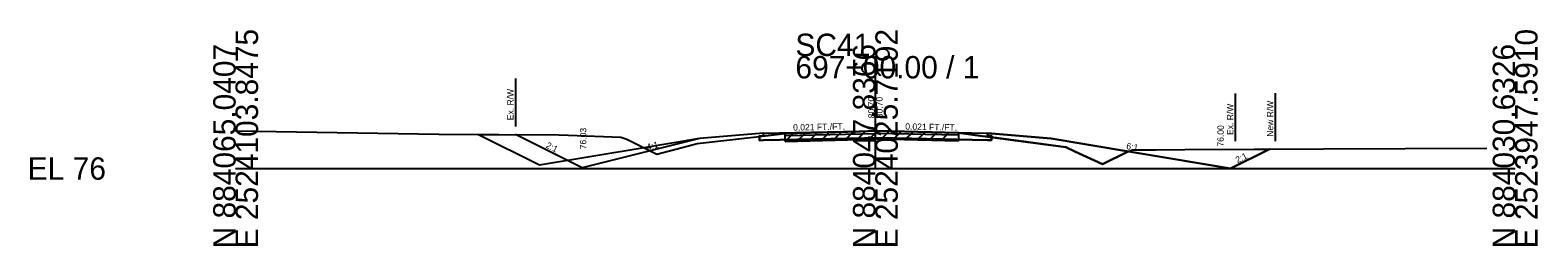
# Model space of a CAD drawing. Extents: x -26 to 183, y -10 to 24021.
# Drawn here: x -25.7 to 162.8, y 20490.3 to 20517.3 of the extents above; entities that cross this region are included whole.
import ezdxf

# ---------------------------------------------------------------- set-up
doc = ezdxf.new("R2010")
doc.units = 0
for name, color, linetype in [('RD_GPK_XS_Cell', 7, 'Continuous'), ('RD_XS_Base', 7, 'Continuous'), ('RD_XS_Buildup', 7, 'Continuous'), ('RD_XS_EarthShd', 7, 'Continuous'), ('RD_XS_EwShp', 7, 'Continuous'), ('RD_XS_ExGround', 7, 'Continuous'), ('RD_XS_ExPaveRet', 7, 'Continuous'), ('RD_XS_ExRW', 7, 'Continuous'), ('RD_XS_NewRW', 7, 'Continuous'), ('RD_XS_Pave', 7, 'Continuous'), ('RD_XS_TieSlope', 7, 'Continuous'), ('RD_XS_TX_Elev_EX', 7, 'Continuous'), ('RD_XS_TX_Elev_PR', 7, 'Continuous'), ('RD_XS_TX_Slope', 7, 'Continuous')]:
    doc.layers.add(name, color=color, linetype=linetype)

msp = doc.modelspace()

# ---------------------------------------------------------------- linework, layer by layer
at = {"layer": 'RD_GPK_XS_Cell'}
for p, q in [((80, 20500), (80, 20514.09)), ((0, 20500), (80, 20500)), ((80, 20500), (160, 20500))]:
    msp.add_line(p, q, dxfattribs=at)
at = {"layer": 'RD_XS_Base'}
for p in [(66.01, 20503.54), (93.99, 20503.57)]:
    msp.add_line(p, (80.72, 20503.84), dxfattribs=at)
at = {"layer": 'RD_XS_Buildup'}
for p in [(68.74, 20504.15), (90.4, 20504.16)]:
    msp.add_line(p, (80, 20504.38), dxfattribs=at)
at = {"layer": 'RD_XS_EarthShd'}
for p, q in [((66, 20504.41), (58, 20503.74)), ((94, 20504.41), (102, 20503.74))]:
    msp.add_line(p, q, dxfattribs=at)
at = {"layer": 'RD_XS_EwShp'}
for points in [[(30.29, 20504.27), (40.43, 20504.2), (41.62, 20504.18), (48.19, 20503.94), (48.94, 20503.66), (51.08, 20502.59), (38, 20500.41)], [(41.62, 20504.18), (48.19, 20503.94), (48.94, 20503.66), (51.08, 20502.59), (38, 20500.41), (30.29, 20504.27), (40.43, 20504.2)], [(41.62, 20504.18), (48.19, 20503.94), (48.94, 20503.66), (51.08, 20502.59), (38, 20500.41), (30.29, 20504.27), (40.43, 20504.2)], [(58, 20503.74), (51.08, 20502.59), (52.69, 20501.78), (56.63, 20502.83), (57.73, 20503.14), (65.5, 20504.03), (65.5, 20504.08), (66, 20504.09), (66, 20504.41)], [(66, 20504.09), (66, 20504.41), (58, 20503.74), (51.08, 20502.59), (52.69, 20501.78), (56.63, 20502.83), (57.73, 20503.14), (65.5, 20504.03), (65.5, 20504.08)], [(66, 20504.09), (66, 20504.41), (58, 20503.74), (51.08, 20502.59), (52.69, 20501.78), (56.63, 20502.83), (57.73, 20503.14), (65.5, 20504.03), (65.5, 20504.08)], [(65.5, 20503.53), (65.5, 20504.03), (66, 20504.09), (66.6, 20504.15), (68.74, 20504.4), (78.1, 20504.65), (80.08, 20504.7), (81.92, 20504.66), (90.4, 20504.48), (93.41, 20504.06), (94.5, 20503.92), (94.5, 20503.56), (93.99, 20503.57), (80.72, 20503.84), (66.01, 20503.54)], [(94.5, 20503.56), (94.5, 20503.92), (93.41, 20504.06), (90.4, 20504.48), (81.92, 20504.66), (80.08, 20504.7), (78.1, 20504.65), (68.74, 20504.4), (66.6, 20504.15), (66, 20504.09), (65.5, 20504.03), (65.5, 20503.53), (66.01, 20503.54), (80.72, 20503.84), (93.99, 20503.57)], [(94.5, 20503.56), (94.5, 20503.92), (93.41, 20504.06), (90.4, 20504.48), (81.92, 20504.66), (80.08, 20504.7), (78.1, 20504.65), (68.74, 20504.4), (66.6, 20504.15), (66, 20504.09), (65.5, 20504.03), (65.5, 20503.53), (66.01, 20503.54), (80.72, 20503.84), (93.99, 20503.57)], [(94.5, 20504.11), (94, 20504.12), (94, 20504.41), (102, 20503.74), (111.66, 20502.13), (111.52, 20502.07), (108.41, 20500.53), (104.95, 20502.12), (103.83, 20502.68), (94.5, 20503.92)], [(104.95, 20502.12), (108.41, 20500.53), (111.52, 20502.07), (111.66, 20502.13), (102, 20503.74), (94, 20504.41), (94, 20504.12), (94.5, 20504.11), (94.5, 20503.92), (103.83, 20502.68)], [(104.95, 20502.12), (108.41, 20500.53), (111.52, 20502.07), (111.66, 20502.13), (102, 20503.74), (94, 20504.41), (94, 20504.12), (94.5, 20504.11), (94.5, 20503.92), (103.83, 20502.68)], [(111.66, 20502.13), (112.15, 20502.35), (115.1, 20502.35), (118.68, 20502.38), (129.27, 20502.43), (124.42, 20500.01)], [(111.66, 20502.13), (112.15, 20502.35), (115.1, 20502.35), (118.68, 20502.38), (129.27, 20502.43), (124.42, 20500.01)], [(111.66, 20502.13), (112.15, 20502.35), (115.1, 20502.35), (118.68, 20502.38), (129.27, 20502.43), (124.42, 20500.01)]]:
    msp.add_lwpolyline(points, close=True, dxfattribs=at)
at = {"layer": 'RD_XS_ExGround'}
for p, q in [((0, 20504.7), (25.4, 20504.3)), ((25.4, 20504.3), (40.43, 20504.2)), ((40.43, 20504.2), (41.62, 20504.18)), ((41.62, 20504.18), (48.19, 20503.94)), ((48.19, 20503.94), (48.94, 20503.66)), ((48.94, 20503.66), (52.69, 20501.78)), ((56.63, 20502.83), (57.73, 20503.14)), ((57.73, 20503.14), (66.6, 20504.15)), ((66.6, 20504.15), (68.74, 20504.4)), ((68.74, 20504.4), (78.1, 20504.65)), ((78.1, 20504.65), (80.08, 20504.7)), ((80.08, 20504.7), (81.92, 20504.66)), ((81.92, 20504.66), (90.4, 20504.48)), ((90.4, 20504.48), (93.41, 20504.06)), ((93.41, 20504.06), (103.83, 20502.68)), ((52.69, 20501.78), (56.63, 20502.83)), ((103.83, 20502.68), (104.95, 20502.12)), ((104.95, 20502.12), (108.41, 20500.53)), ((108.41, 20500.53), (111.52, 20502.07)), ((111.52, 20502.07), (112.15, 20502.35)), ((112.15, 20502.35), (115.1, 20502.35)), ((115.1, 20502.35), (118.68, 20502.38)), ((118.68, 20502.38), (136.04, 20502.46)), ((136.04, 20502.46), (156.45, 20502.53))]:
    msp.add_line(p, q, dxfattribs=at)
at = {"layer": 'RD_XS_ExPaveRet'}
for p, q in [((68.74, 20503.4), (69.76, 20504.43)), ((68.74, 20503.4), (68.74, 20504.4)), ((68.74, 20503.4), (78.1, 20503.65)), ((70.24, 20503.44), (71.26, 20504.47)), ((71.74, 20503.48), (72.76, 20504.51)), ((73.24, 20503.52), (74.26, 20504.55)), ((74.74, 20503.56), (75.76, 20504.58)), ((76.24, 20503.6), (77.26, 20504.62)), ((77.74, 20503.64), (78.76, 20504.66)), ((78.1, 20503.65), (80.08, 20503.7)), ((79.24, 20503.68), (80.26, 20504.69)), ((80.08, 20503.7), (81.92, 20503.66)), ((80.74, 20503.68), (81.72, 20504.66)), ((81.92, 20503.66), (90.4, 20503.48)), ((82.24, 20503.65), (83.22, 20504.63)), ((83.74, 20503.62), (84.72, 20504.6)), ((85.24, 20503.59), (86.22, 20504.57)), ((86.74, 20503.56), (87.72, 20504.54)), ((88.24, 20503.53), (89.22, 20504.51)), ((90.4, 20504.48), (90.4, 20503.48))]:
    msp.add_line(p, q, dxfattribs=at)
at = {"layer": 'RD_XS_ExRW'}
for p, q in [((35, 20511.27), (35, 20505.27)), ((125, 20509.41), (125, 20503.41))]:
    msp.add_line(p, q, dxfattribs=at)
at = {"layer": 'RD_XS_NewRW'}
msp.add_line((130.01, 20509.44), (130.01, 20503.44), dxfattribs=at)
at = {"layer": 'RD_XS_Pave'}
for p, q in [((65.5, 20504.08), (66, 20504.09)), ((65.5, 20503.53), (65.5, 20504.08)), ((65.5, 20503.53), (66.01, 20503.54)), ((66, 20504.41), (80, 20504.7)), ((66, 20504.09), (66, 20504.41)), ((80, 20504.7), (94, 20504.41)), ((94.5, 20503.56), (93.99, 20503.57)), ((94, 20504.12), (94, 20504.41)), ((94.5, 20504.11), (94, 20504.12)), ((94.5, 20503.56), (94.5, 20504.11))]:
    msp.add_line(p, q, dxfattribs=at)
at = {"layer": 'RD_XS_TieSlope'}
for p, q in [((43.33, 20500.07), (35, 20504.24)), ((58, 20503.74), (43.33, 20500.07)), ((102, 20503.74), (124.42, 20500.01)), ((124.42, 20500.01), (129.27, 20502.43))]:
    msp.add_line(p, q, dxfattribs=at)

# ---------------------------------------------------------------- texts
at = {"layer": 'RD_GPK_XS_Cell'}
for s, p in [('E 2524103.8475', (2.8, 20490)), ('E 2524025.7192', (82.8, 20490)), ('E 2523947.5910', (162.8, 20490)), ('N 884065.0407', (0, 20490)), ('N 884047.8366', (80, 20490)), ('N 884030.6326', (160, 20490))]:
    msp.add_text(s, height=2.8, rotation=90, dxfattribs=at).set_placement(p)
for s, p in [('SC41', (70, 20514.09)), ('697+00.00 / 1', (70, 20511.29)), ('EL 76', (-26, 20498.6))]:
    msp.add_text(s, height=2.8, dxfattribs=at).set_placement(p)
at = {"layer": 'RD_XS_ExRW'}
for p in [(34.75, 20506.05), (124.75, 20504.2)]:
    msp.add_text('Ex. R/W ', height=0.8, rotation=90, dxfattribs=at).set_placement(p)
at = {"layer": 'RD_XS_NewRW'}
msp.add_text('New R/W ', height=0.8, rotation=90, dxfattribs=at).set_placement((129.76, 20503.98))
at = {"layer": 'RD_XS_TX_Elev_EX'}
msp.add_text('80.70', height=0.8, rotation=90, dxfattribs=at).set_placement((79.9, 20506.3))
at = {"layer": 'RD_XS_TX_Elev_PR'}
for s, p in [('80.70', (80.9, 20506.3)), ('76.03', (43.86, 20502.41)), ('76.00', (123.57, 20502.75))]:
    msp.add_text(s, height=0.8, rotation=90, dxfattribs=at).set_placement(p)
at = {"layer": 'RD_XS_TX_Slope'}
for s, rotation, p in [('0.021 FT./FT.', 1.1916, (69.72, 20504.74)), ('0.021 FT./FT.', 358.8084, (83.73, 20504.87)), ('2:1', 333.4349, (38.72, 20502.65)), ('4:1', 14.0362, (51.5, 20502.28)), ('6:1', 350.5377, (111.33, 20502.44)), ('2:1', 26.5651, (125.28, 20500.65))]:
    msp.add_text(s, height=0.8, rotation=rotation, dxfattribs=at).set_placement(p)

doc.saveas('drawing.dxf')
